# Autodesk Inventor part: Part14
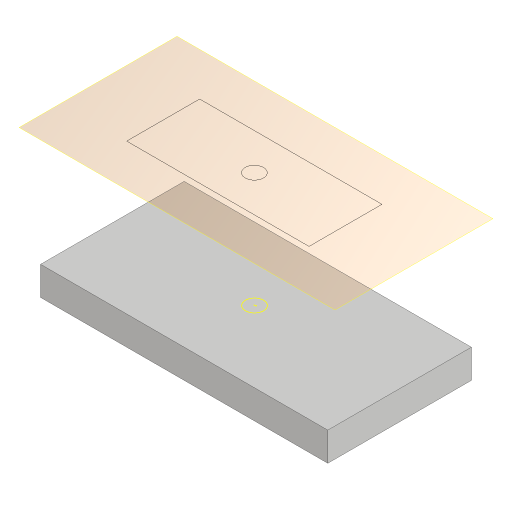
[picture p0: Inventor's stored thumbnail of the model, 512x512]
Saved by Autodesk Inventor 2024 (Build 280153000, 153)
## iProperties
Created: 2015-05
Part Number: Part14
Material: Generic
Document SubType Name: Modeling
Designer: Sandeep
Density: 1 g/cm^3
Appearance: Default
Author: Sandeep
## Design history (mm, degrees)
sketch "Sketch1"
  geometry: L1 (-100, 50)-(100, 50); L2 (100, 50)-(100, -50); L3 (100, -50)-(-100, -50); L4 (-100, -50)-(-100, 50); 1 further point
  constraints: 8 end point, 2 parallel, 1 horizontal, 1 perpendicular
  dimensions: "d0" = 100 distance from line of point (0, 0) L2; "d1" = 200 distance of L1.start L1.end; "d2" = 50 distance from line of point (0, 0) L1; "d3" = 100 distance of L1.end L2.end
extrude "Extrusion1" new body sketch "Sketch1" distance "d4" = 20; taper "d5" = 0 deg
workplane "Work Plane1"
body "Solid1"
sketch "Sketch2"
  geometry: C1 r 6.35 at (-0.807, -0.346) reference; 1 further point
